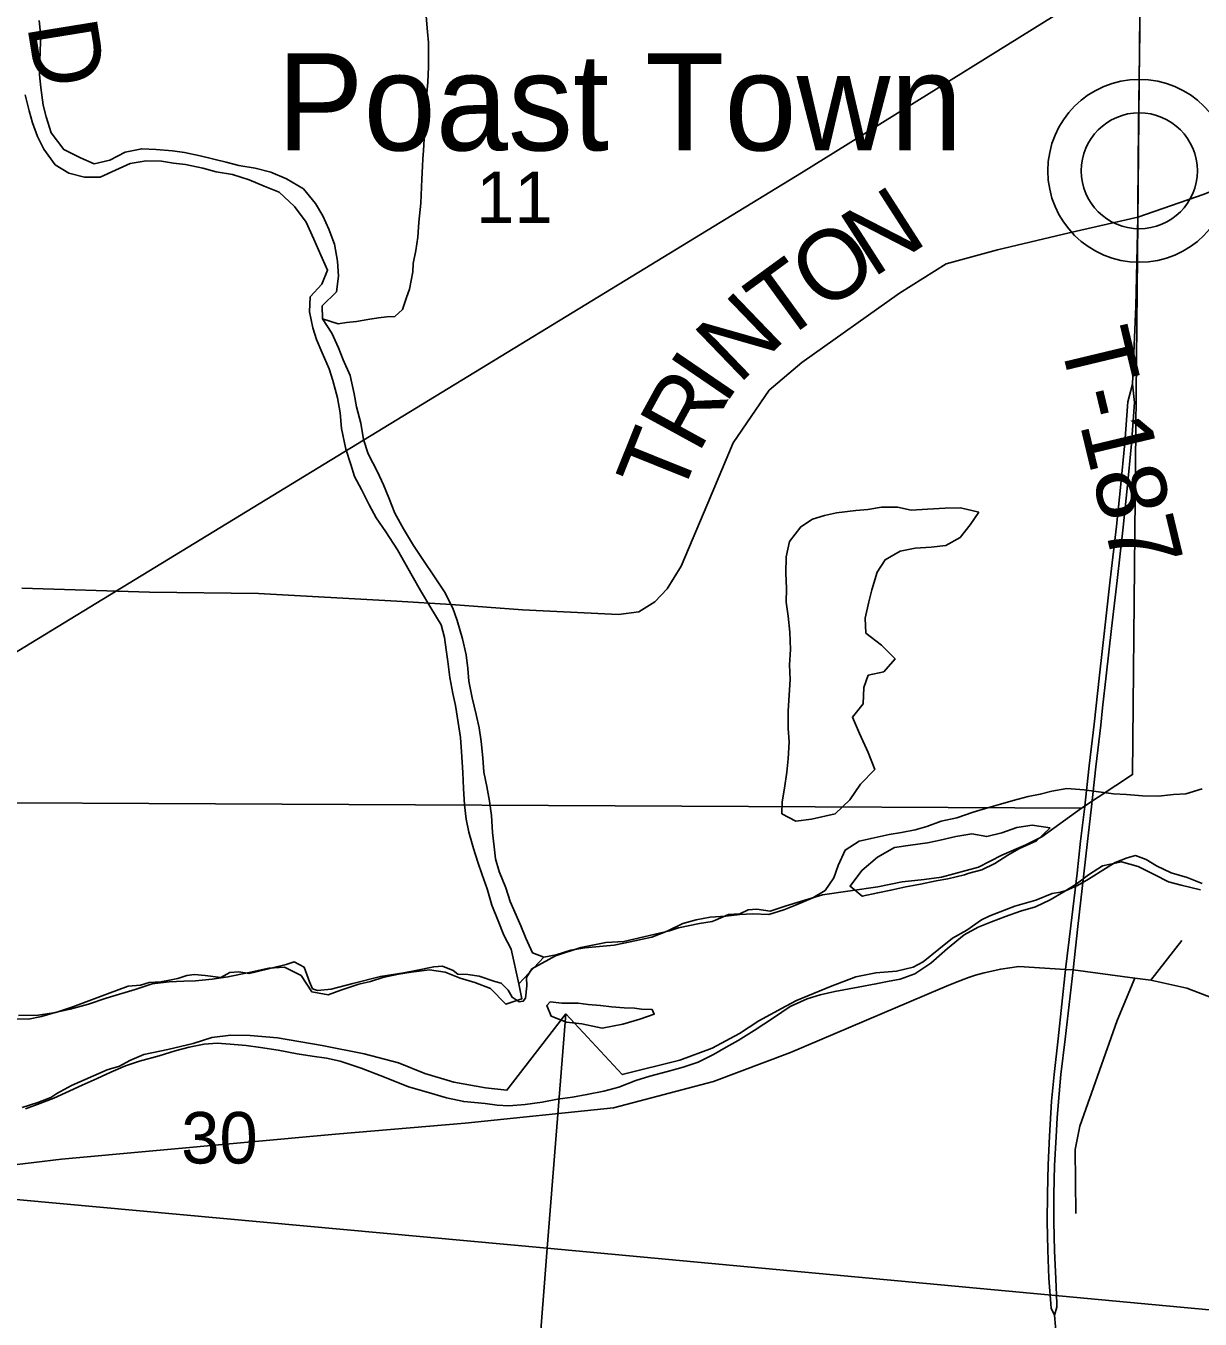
# Model space of a CAD drawing. Extents: x 0 to 34, y 0 to 22.
# Drawn here: x 6.323 to 7.278, y 18.713 to 19.765 of the extents above; entities that cross this region are included whole.
import ezdxf

# ---------------------------------------------------------------- set-up
doc = ezdxf.new("R2010")
doc.units = 0
for name, color, linetype in [('GM_X_City_Street', 7, 'Continuous'), ('GM_X_Corporation', 7, 'Continuous'), ('GM_X_County_Road', 7, 'Continuous'), ('GM_X_County_Road_Text', 7, 'Continuous'), ('GM_X_Major_River', 7, 'Continuous'), ('GM_X_Minor_River', 7, 'Continuous'), ('GM_X_Rail_Line', 7, 'Continuous'), ('GM_X_Section_Text', 7, 'Continuous'), ('GM_X_State_Route', 7, 'Continuous'), ('GM_X_Township_Road_Text', 7, 'Continuous'), ('GM_X_Unincorporated', 7, 'Continuous'), ('GM_X_Unincorporated_Location', 7, 'Continuous'), ('GM_X_Unincorporated_Text', 7, 'Continuous')]:
    doc.layers.add(name, color=color, linetype=linetype)

msp = doc.modelspace()

# ---------------------------------------------------------------- linework, layer by layer
at = {"layer": 'GM_X_City_Street'}
msp.add_line((7.2376, 18.9889), (7.2628, 19.0212), dxfattribs=at)
for points in [[(7.1744, 18.9974), (7.2247, 18.9906), (7.2376, 18.9889), (7.2669, 18.9824), (7.3145, 18.9643), (7.3951, 18.9322), (7.4412, 18.9129), (7.509, 18.9037), (7.6408, 18.8847), (7.6785, 18.8798), (7.7053, 18.8743), (7.7287, 18.8668), (7.7608, 18.8473), (7.7795, 18.8294), (7.7959, 18.8068), (7.8336, 18.7488), (7.8673, 18.6946), (7.8728, 18.686)], [(7.1767, 18.7991), (7.1761, 18.8512), (7.1798, 18.8702), (7.2103, 18.9563), (7.2247, 18.9906)]]:
    msp.add_lwpolyline(points, dxfattribs=at)
at = {"layer": 'GM_X_Corporation'}
msp.add_lwpolyline([(6.2147, 20.1499), (7.2322, 20.1409), (7.2228, 19.1563), (7.1813, 19.1288), (6.2057, 19.1338)], close=True, dxfattribs=at)
for points in [[(6.2057, 19.1338), (7.1813, 19.1288), (7.149, 19.1056), (7.136, 19.0991), (7.1165, 19.0908), (7.0974, 19.0809), (7.0673, 19.0729), (7.0532, 19.0709), (7.0354, 19.069), (7.0156, 19.0649), (6.9707, 19.0583), (6.941, 19.0495), (6.928, 19.0452), (6.9171, 19.0469), (6.9103, 19.0463), (6.9034, 19.0431), (6.8943, 19.0425), (6.8836, 19.0378), (6.8809, 19.0367), (6.8706, 19.0351), (6.8535, 19.0316), (6.8463, 19.0291), (6.809, 19.0205), (6.7945, 19.0196), (6.774, 19.0155), (6.7534, 19.0088), (6.7342, 18.9982), (6.7299, 18.9911), (6.7301, 18.9843), (6.7292, 18.9745), (6.7272, 18.9719), (6.7238, 18.9715), (6.7182, 18.9751), (6.7149, 18.9808), (6.7094, 18.9866), (6.7041, 18.9879), (6.6913, 18.9923), (6.6822, 18.9937), (6.6739, 18.9938), (6.6702, 18.9969), (6.6616, 19.0005), (6.6544, 18.9999), (6.6399, 18.9968), (6.63, 18.9951), (6.611, 18.9921), (6.5885, 18.9862), (6.571, 18.9816), (6.56, 18.9807), (6.5559, 18.982), (6.5533, 18.9877), (6.549, 18.9995), (6.5408, 19.0039), (6.5343, 19.0018), (6.51, 18.9958), (6.5042, 18.9944), (6.4959, 18.9958), (6.4887, 18.9952), (6.4814, 18.9911), (6.4686, 18.9929), (6.4599, 18.9935), (6.4535, 18.9929), (6.4462, 18.9904), (6.4394, 18.989), (6.4325, 18.9877), (6.423, 18.9871), (6.4158, 18.985), (6.4059, 18.9841), (6.3891, 18.978), (6.3609, 18.9672), (6.3471, 18.9626), (6.3327, 18.9606), (6.3168, 18.9602)], [(7.7682, 18.6757), (6.7468, 18.7711), (6.7619, 18.9616), (6.8078, 18.9122), (6.8546, 18.924), (6.881, 18.9337), (6.9032, 18.9457), (6.9189, 18.956), (6.9408, 18.968), (6.9496, 18.9724), (6.9771, 18.9839), (6.9977, 18.9918), (7.0141, 18.9949), (7.0308, 18.9964), (7.0445, 18.9995), (7.0525, 19.0039), (7.0652, 19.0142), (7.0764, 19.0231), (7.0879, 19.0296), (7.0999, 19.0381), (7.1067, 19.0413), (7.127, 19.0493), (7.1441, 19.0542), (7.1575, 19.0596), (7.1643, 19.0606), (7.1689, 19.062), (7.1781, 19.066), (7.1869, 19.0711), (7.2007, 19.0799), (7.2088, 19.0846), (7.2184, 19.0886), (7.2252, 19.0903), (7.2338, 19.0871), (7.2424, 19.082), (7.2541, 19.0764), (7.2672, 19.0724), (7.2793, 19.0676)], [(6.3197, 18.8855), (6.3323, 18.8894), (6.343, 18.8937), (6.348, 18.8967), (6.3599, 18.9032), (6.3889, 18.9162), (6.3988, 18.9191), (6.4073, 18.9238), (6.4187, 18.9285), (6.4381, 18.9326), (6.4587, 18.9375), (6.474, 18.9424), (6.4895, 18.9444), (6.5051, 18.944), (6.5274, 18.9421), (6.5636, 18.936), (6.5979, 18.9292), (6.6258, 18.9218), (6.6472, 18.913), (6.6709, 18.906), (6.6966, 18.9013), (6.7139, 18.8994), (6.7619, 18.9616), (6.7468, 18.7711), (5.8856, 18.8498)], [(5.7386, 18.6518), (5.7481, 18.6739), (5.7533, 18.6863), (5.7584, 18.6927), (5.7787, 18.7199), (5.7947, 18.7434), (5.8001, 18.7493), (5.8105, 18.754), (5.8223, 18.758), (5.8345, 18.763), (5.8411, 18.7693), (5.8474, 18.7813), (5.8537, 18.7914), (5.8588, 18.7988), (5.8704, 18.8118), (5.8793, 18.8207), (5.8856, 18.8498), (6.7468, 18.7711), (6.6697, 17.7728), (6.0867, 17.8254), (5.7275, 17.9786)], [(7.7361, 18.0529), (7.7161, 17.6636), (6.6697, 17.7728), (6.7468, 18.7711), (7.7682, 18.6757), (7.7459, 18.2415)]]:
    msp.add_lwpolyline(points, dxfattribs=at)
at = {"layer": 'GM_X_County_Road'}
for points in [[(7.2271, 19.6098), (7.2811, 19.6284), (7.3162, 19.6427), (7.3984, 19.6777), (7.4886, 19.7223), (7.5157, 19.7379), (7.5777, 19.7818), (7.6742, 19.8562), (7.7116, 19.8844), (7.7542, 19.9166), (7.7862, 19.9347), (7.8333, 19.9572), (7.8737, 19.9675), (7.91, 19.9746), (7.988, 19.9925), (8.0578, 20.005), (8.1281, 20.0204), (8.2142, 20.0385), (8.2414, 20.0445)], [(6.3193, 19.308), (6.4232, 19.3046), (6.5119, 19.3035), (6.6243, 19.2974), (6.6685, 19.2946), (6.7265, 19.2904), (6.8048, 19.2865), (6.8213, 19.2886), (6.8343, 19.2967), (6.8443, 19.3074), (6.8556, 19.3257), (6.8775, 19.3771), (6.898, 19.426), (6.9272, 19.4689), (6.9539, 19.4914), (7.0332, 19.5478), (7.0712, 19.5716), (7.1131, 19.5832), (7.1713, 19.597), (7.2271, 19.6098)], [(5.9634, 18.7111), (6.0575, 18.7524), (6.1407, 18.7864), (6.2264, 18.8212), (6.2838, 18.8353), (6.3516, 18.8433), (6.5744, 18.8637), (6.6801, 18.8728), (6.8006, 18.8851), (6.882, 18.9065), (6.9447, 18.9302), (7.0662, 18.982), (7.0748, 18.9856), (7.0823, 18.9886), (7.0895, 18.9911), (7.0951, 18.993), (7.1022, 18.9949), (7.1156, 18.998), (7.1303, 19.0001), (7.1684, 18.9978), (7.1744, 18.9974)]]:
    msp.add_lwpolyline(points, dxfattribs=at)
at = {"layer": 'GM_X_Major_River'}
msp.add_line((6.7441, 19.0076), (6.7236, 18.9859), dxfattribs=at)
for points in [[(7.2794, 19.1446), (7.2661, 19.1407), (7.2562, 19.1401), (7.244, 19.1388), (7.2308, 19.1391), (7.2179, 19.1401), (7.2073, 19.1407), (7.1933, 19.1425), (7.1834, 19.1438), (7.1694, 19.1449), (7.1572, 19.1428), (7.1477, 19.1403), (7.1378, 19.1383), (7.1256, 19.1351), (7.1153, 19.1322), (7.1058, 19.1294), (7.0932, 19.1258), (7.0798, 19.1211), (7.0672, 19.1184), (7.0554, 19.114), (7.0459, 19.1112), (7.0348, 19.1091), (7.0249, 19.1074), (7.0101, 19.1043), (7.0005, 19.1022), (6.989, 19.0948), (6.9834, 19.0824), (6.9798, 19.0722), (6.9728, 19.062), (6.9628, 19.0561), (6.9487, 19.05), (6.9391, 19.0463), (6.9269, 19.0424), (6.9136, 19.043), (6.9034, 19.0425), (6.892, 19.0412), (6.8794, 19.0403), (6.868, 19.0382), (6.8569, 19.035), (6.8443, 19.0288), (6.8317, 19.0241), (6.8142, 19.0203), (6.8012, 19.0175), (6.7773, 19.0153), (6.7659, 19.0133), (6.754, 19.0097)], [(7.1559, 19.1128), (7.1411, 19.115), (7.1286, 19.1133), (7.1164, 19.109), (7.1042, 19.1058), (7.0921, 19.108), (7.0791, 19.106), (7.0662, 19.1028), (7.0559, 19.1007), (7.0422, 19.0987), (7.0293, 19.097), (7.0154, 19.089), (7.0027, 19.0782), (6.993, 19.0654), (7.003, 19.0573), (7.0156, 19.0601), (7.0263, 19.0621), (7.0385, 19.0649), (7.0503, 19.067), (7.0632, 19.0698), (7.0727, 19.0715), (7.0861, 19.0746)], [(7.0861, 19.0746), (7.0899, 19.0761), (7.1002, 19.0789), (7.1109, 19.084), (7.1213, 19.0907), (7.1309, 19.0962), (7.1447, 19.1024), (7.1559, 19.1128)], [(6.7672, 18.8939), (6.779, 18.8959), (6.7927, 18.8987), (6.8049, 18.9019), (6.8187, 18.9073), (6.8302, 18.9109), (6.8446, 18.9148), (6.8572, 18.9183), (6.8694, 18.9223), (6.8821, 18.9285), (6.8924, 18.9344), (6.902, 18.9399), (6.9151, 18.948), (6.9309, 18.9583), (6.9443, 18.9675), (6.9581, 18.9737), (6.9688, 18.977), (6.9806, 18.9798), (6.9996, 18.9832), (7.0141, 18.986), (7.0236, 18.988), (7.0339, 18.9897), (7.0458, 18.9941), (7.0588, 19.0029), (7.0723, 19.0148), (7.0858, 19.026), (7.0973, 19.0322), (7.1081, 19.0366), (7.1195, 19.0409), (7.1317, 19.0452), (7.144, 19.0488), (7.1558, 19.0543), (7.167, 19.0609), (7.1769, 19.0672), (7.187, 19.0746), (7.1985, 19.0819), (7.2137, 19.0854), (7.2273, 19.0814), (7.2408, 19.0746), (7.2521, 19.0691), (7.2623, 19.0662), (7.2781, 19.0625)], [(6.754, 19.0097), (6.7441, 19.0076)], [(6.7236, 18.9859), (6.726, 18.9737), (6.713, 18.9694), (6.7007, 18.9822), (6.6879, 18.987), (6.6759, 18.9907), (6.6638, 18.9955), (6.651, 18.9973), (6.6362, 18.9956), (6.6259, 18.9939), (6.6129, 18.9912), (6.603, 18.9879), (6.5935, 18.9858), (6.579, 18.9808), (6.5687, 18.9772), (6.5554, 18.9794), (6.5466, 18.9928), (6.5331, 18.9996), (6.5202, 18.9987), (6.5042, 18.9952), (6.487, 18.9917), (6.4741, 18.9897), (6.4608, 18.9884), (6.4513, 18.9883), (6.4392, 18.9877), (6.4255, 18.9861), (6.4117, 18.9814), (6.3881, 18.9743), (6.3736, 18.9696), (6.3587, 18.9654), (6.3465, 18.9626), (6.3354, 18.9594), (6.3248, 18.9573), (6.3153, 18.9575)], [(6.7491, 18.9714), (6.7464, 18.9684), (6.75, 18.9596), (6.7624, 18.9548), (6.7749, 18.9534), (6.7915, 18.95)], [(6.7915, 18.95), (6.8083, 18.9531), (6.822, 18.9574), (6.8338, 18.9614), (6.832, 18.9652), (6.8233, 18.9654), (6.8176, 18.9662), (6.8093, 18.9664), (6.7991, 18.9674), (6.79, 18.9683), (6.7801, 18.9693), (6.7718, 18.9702), (6.7585, 18.9704), (6.7491, 18.9714)], [(6.3225, 18.8843), (6.334, 18.8887), (6.3454, 18.893), (6.355, 18.8974), (6.3684, 18.9036), (6.3807, 18.909), (6.3918, 18.9141), (6.4036, 18.9192), (6.4151, 18.9232), (6.4311, 18.9274), (6.4441, 18.9314), (6.4555, 18.9346), (6.4677, 18.937), (6.4783, 18.9379), (6.4889, 18.9369), (6.5018, 18.9359), (6.5135, 18.9342), (6.5279, 18.932), (6.5434, 18.929), (6.5555, 18.9273), (6.5672, 18.9255), (6.5782, 18.923), (6.5955, 18.9174), (6.6109, 18.9114), (6.6211, 18.9074), (6.6339, 18.9022), (6.6482, 18.8981), (6.6648, 18.8932), (6.6788, 18.8903), (6.6962, 18.8888), (6.706, 18.8874), (6.7155, 18.8869), (6.7288, 18.8878), (6.7425, 18.8898), (6.7551, 18.8922), (6.7672, 18.8939)]]:
    msp.add_lwpolyline(points, dxfattribs=at)
at = {"layer": 'GM_X_Minor_River'}
msp.add_line((6.7236, 18.9859), (6.7441, 19.0076), dxfattribs=at)
for points in [[(6.5639, 19.5271), (6.5766, 19.5228), (6.5834, 19.5239), (6.5917, 19.5249), (6.6008, 19.5264), (6.6095, 19.5278), (6.6163, 19.5285), (6.6228, 19.5288), (6.6289, 19.5345), (6.6323, 19.5443), (6.6346, 19.5511), (6.6362, 19.5583), (6.6374, 19.5651), (6.6378, 19.5719), (6.6398, 19.5825), (6.6414, 19.5935), (6.6422, 19.6057), (6.6439, 19.6212), (6.6448, 19.6405), (6.6452, 19.6512), (6.6456, 19.6572), (6.6461, 19.664), (6.6469, 19.6781), (6.6478, 19.6917), (6.6478, 19.6986), (6.6495, 19.7194), (6.6503, 19.7319), (6.6501, 19.7456), (6.6501, 19.7517), (6.6494, 19.7604), (6.6477, 19.7798)], [(6.5896, 19.4661), (6.5865, 19.481), (6.5807, 19.4937), (6.5771, 19.5033), (6.5716, 19.5152), (6.5639, 19.5271), (6.5637, 19.5377), (6.5753, 19.5489), (6.5771, 19.5618), (6.5762, 19.574), (6.5738, 19.5877), (6.5692, 19.6), (6.5641, 19.6108), (6.5582, 19.6208), (6.5486, 19.6327), (6.5347, 19.641), (6.5219, 19.6462), (6.5091, 19.6495), (6.4959, 19.6516), (6.4857, 19.6545), (6.4645, 19.6595), (6.4517, 19.6624), (6.4419, 19.6637), (6.4286, 19.6648), (6.4169, 19.6654), (6.4035, 19.6626), (6.3909, 19.656), (6.3783, 19.6532), (6.367, 19.658), (6.3535, 19.6647), (6.3432, 19.6782), (6.3393, 19.6912), (6.3368, 19.7008), (6.3348, 19.7153), (6.3339, 19.7256), (6.3343, 19.7457), (6.3349, 19.7564), (6.3336, 19.7697)], [(6.3222, 19.7091), (6.3253, 19.6961), (6.3282, 19.6865), (6.3321, 19.6754), (6.3372, 19.665), (6.3464, 19.6523), (6.3577, 19.6456), (6.3705, 19.6423), (6.383, 19.6421), (6.3957, 19.6479), (6.4075, 19.6534), (6.4205, 19.6554), (6.433, 19.6552), (6.4428, 19.6535), (6.4526, 19.6525), (6.4666, 19.6496), (6.4776, 19.6467), (6.4908, 19.6445), (6.5044, 19.6401), (6.5164, 19.6349), (6.5288, 19.6301), (6.5411, 19.6184), (6.5507, 19.6057), (6.5569, 19.5919), (6.5627, 19.5788), (6.5681, 19.5666), (6.5633, 19.5552), (6.554, 19.5448), (6.5534, 19.5326), (6.5561, 19.5196), (6.559, 19.5101), (6.5637, 19.4993), (6.5695, 19.4863), (6.5723, 19.4767)], [(6.5723, 19.4767), (6.5762, 19.4626), (6.5783, 19.4504), (6.5795, 19.4378), (6.583, 19.421), (6.5869, 19.4084), (6.5901, 19.3988), (6.5956, 19.3881), (6.6018, 19.3758), (6.6076, 19.365), (6.6154, 19.3538), (6.6249, 19.3392), (6.6308, 19.3284), (6.637, 19.318), (6.6436, 19.3061), (6.652, 19.2919), (6.6605, 19.278), (6.6633, 19.2677), (6.6646, 19.2578), (6.6659, 19.2483), (6.6676, 19.2353), (6.67, 19.2223), (6.672, 19.2124), (6.6744, 19.1987), (6.6761, 19.1865), (6.677, 19.1747), (6.6781, 19.1579), (6.6786, 19.145), (6.6795, 19.1317), (6.6808, 19.1199), (6.6829, 19.1095), (6.6868, 19.0962), (6.6903, 19.0851), (6.6939, 19.0747), (6.6978, 19.0632), (6.7017, 19.0499), (6.7068, 19.0372), (6.7115, 19.0257), (6.7173, 19.0142), (6.7236, 18.9859)], [(6.7441, 19.0076), (6.7347, 19.0112), (6.7293, 19.0231), (6.7253, 19.0331), (6.7166, 19.053), (6.713, 19.0641), (6.7076, 19.0775), (6.7048, 19.0878), (6.7035, 19.0974), (6.7022, 19.1092), (6.7013, 19.1229), (6.6997, 19.1347), (6.6976, 19.1465), (6.6952, 19.1583), (6.6943, 19.1698), (6.6931, 19.1831), (6.6914, 19.1942), (6.689, 19.2052), (6.6858, 19.2186), (6.6831, 19.2323), (6.6821, 19.2426), (6.6808, 19.2537), (6.6777, 19.2667), (6.6734, 19.2816), (6.6699, 19.2915), (6.6633, 19.305), (6.6541, 19.3188), (6.6467, 19.3296), (6.6379, 19.3427), (6.6298, 19.3562), (6.6229, 19.3689), (6.6178, 19.3815), (6.6135, 19.3919), (6.6088, 19.4026), (6.6011, 19.4172), (6.5972, 19.4287), (6.5952, 19.4421), (6.5916, 19.4554), (6.5896, 19.4661)], [(7.083, 19.3732), (7.0705, 19.373), (7.0561, 19.3722), (7.0428, 19.3713), (7.0315, 19.3738), (7.0186, 19.3737), (7.0075, 19.372), (6.9977, 19.371), (6.9821, 19.3691), (6.9722, 19.367), (6.9626, 19.3641), (6.953, 19.3578), (6.9437, 19.3459), (6.9411, 19.3334), (6.9409, 19.3201), (6.9414, 19.3075), (6.9411, 19.2965), (6.9428, 19.285), (6.9441, 19.2721), (6.9445, 19.258), (6.9439, 19.2455), (6.9444, 19.2337), (6.9434, 19.2208), (6.9428, 19.2082), (6.9428, 19.1938), (6.9434, 19.1828), (6.9427, 19.1691), (6.9417, 19.1581), (6.9396, 19.1452), (6.9378, 19.1342), (6.9376, 19.1243)], [(6.9376, 19.1243), (6.9489, 19.1184), (6.9618, 19.12), (6.9809, 19.1242), (6.9929, 19.1358), (7.0015, 19.1485), (7.0131, 19.1605), (7.0077, 19.1743), (7.0008, 19.1896), (6.995, 19.203), (7.0036, 19.2139), (7.0042, 19.2272), (7.0078, 19.237), (7.0204, 19.2398), (7.0297, 19.2503), (7.0186, 19.2615), (7.0059, 19.2713), (7.0054, 19.2834), (7.0083, 19.2967), (7.0108, 19.3065), (7.0152, 19.3209), (7.0215, 19.331), (7.0338, 19.338), (7.046, 19.3404), (7.0589, 19.3413), (7.071, 19.3426), (7.0825, 19.3492), (7.0907, 19.3593), (7.0978, 19.3698)], [(7.0978, 19.3698), (7.083, 19.3732)]]:
    msp.add_lwpolyline(points, dxfattribs=at)
at = {"layer": 'GM_X_Rail_Line'}
msp.add_lwpolyline([(5.7307, 18.8031), (5.7764, 18.8589), (5.8381, 18.9243), (5.8849, 18.9665), (5.9458, 19.0195), (6.0144, 19.069), (6.0845, 19.1134), (6.1841, 19.1748), (6.2736, 19.231), (6.831, 19.571), (6.9536, 19.6458), (7.2249, 19.8148)], dxfattribs=at)
at = {"layer": 'GM_X_State_Route'}
for points in [[(7.2287, 19.7607), (7.2294, 19.8131), (7.2311, 19.9626)], [(7.2272, 19.6199), (7.2277, 19.6841), (7.2287, 19.7607)], [(7.2227, 19.4739), (7.2255, 19.537), (7.2271, 19.6098), (7.2272, 19.6199)], [(7.1684, 18.9978), (7.1727, 19.0332), (7.1777, 19.076), (7.1806, 19.102), (7.1836, 19.1282), (7.1876, 19.1633), (7.1915, 19.1972), (7.1959, 19.2372), (7.2002, 19.2757), (7.2047, 19.3147), (7.2098, 19.3583), (7.2131, 19.3898), (7.2164, 19.4261), (7.2191, 19.4596), (7.2227, 19.4739)], [(7.1985, 19.2105), (7.2014, 19.2365), (7.2057, 19.275), (7.2102, 19.314), (7.2152, 19.3576), (7.2185, 19.3891), (7.2219, 19.4254), (7.2245, 19.4589), (7.2227, 19.4739)], [(7.1871, 19.109), (7.1892, 19.1275), (7.193, 19.1626), (7.1969, 19.1965), (7.1985, 19.2105)], [(7.1616, 18.877), (7.1625, 18.8903), (7.1646, 18.9123), (7.1679, 18.9409), (7.1744, 18.9974), (7.1784, 19.0327), (7.1833, 19.0755), (7.1862, 19.1018), (7.1871, 19.109)], [(7.1594, 18.7164), (7.1566, 18.7223), (7.1548, 18.7466), (7.1538, 18.7693), (7.1534, 18.7926), (7.1535, 18.8151), (7.1541, 18.8387), (7.1552, 18.862), (7.157, 18.8905), (7.1591, 18.9124), (7.1623, 18.9412), (7.1684, 18.9978)], [(7.1611, 18.7261), (7.1603, 18.7461), (7.1594, 18.7689), (7.1588, 18.7923), (7.1589, 18.8147), (7.1594, 18.8383), (7.1606, 18.8617), (7.1616, 18.877)], [(7.1594, 18.7164), (7.1612, 18.7231), (7.1611, 18.7261)], [(7.2285, 18.2415), (7.2258, 18.2453), (7.2129, 18.2652), (7.2044, 18.2822), (7.2003, 18.2939), (7.1955, 18.3107), (7.1922, 18.3294), (7.1903, 18.3468), (7.1892, 18.3601), (7.1871, 18.3813), (7.1839, 18.4133), (7.1788, 18.486), (7.1712, 18.5731), (7.1602, 18.7074), (7.1594, 18.7164)]]:
    msp.add_lwpolyline(points, dxfattribs=at)
at = {"layer": 'GM_X_Unincorporated'}
for radius in [0.0744, 0.0472]:
    msp.add_circle((7.2283, 19.6474), radius, dxfattribs=at)
at = {"layer": 'GM_X_Unincorporated_Location'}
msp.add_line((7.2283, 19.6474), (7.2283, 19.6474), dxfattribs=at)

# ---------------------------------------------------------------- texts
at = {"layer": 'GM_X_County_Road_Text'}
for s, rotation, p in [('N', 32.6948, (7.0113, 19.5597)), ('O', 35.1794, (6.971, 19.5313)), ('T', 36.0668, (6.9368, 19.5064)), ('N', 43.9451, (6.9024, 19.473)), ('I', 55.6756, (6.8912, 19.4561)), ('R', 61.3033, (6.8696, 19.4164)), ('T', 68.1417, (6.8545, 19.3786))]:
    msp.add_text(s, height=0.0568, rotation=rotation, dxfattribs=at).set_placement(p)
at = {"layer": 'GM_X_Section_Text'}
for s, p in [('11', (6.689, 19.6049)), ('30', (6.449, 18.8399))]:
    msp.add_text(s, height=0.04186, rotation=0, dxfattribs=at).set_placement(p)
at = {"layer": 'GM_X_Township_Road_Text'}
for s, height, rotation, p in [('D', 0.0568, 279.2163, (6.3236, 19.7658)), ('T-187', 0.05682, 283.4933, (7.163, 19.5114))]:
    msp.add_text(s, height=height, rotation=rotation, dxfattribs=at).set_placement(p)
at = {"layer": 'GM_X_Unincorporated_Text'}
msp.add_text('Poast Town', height=0.07898, rotation=0, dxfattribs=at).set_placement((6.5269, 19.664))

doc.saveas('drawing.dxf')
